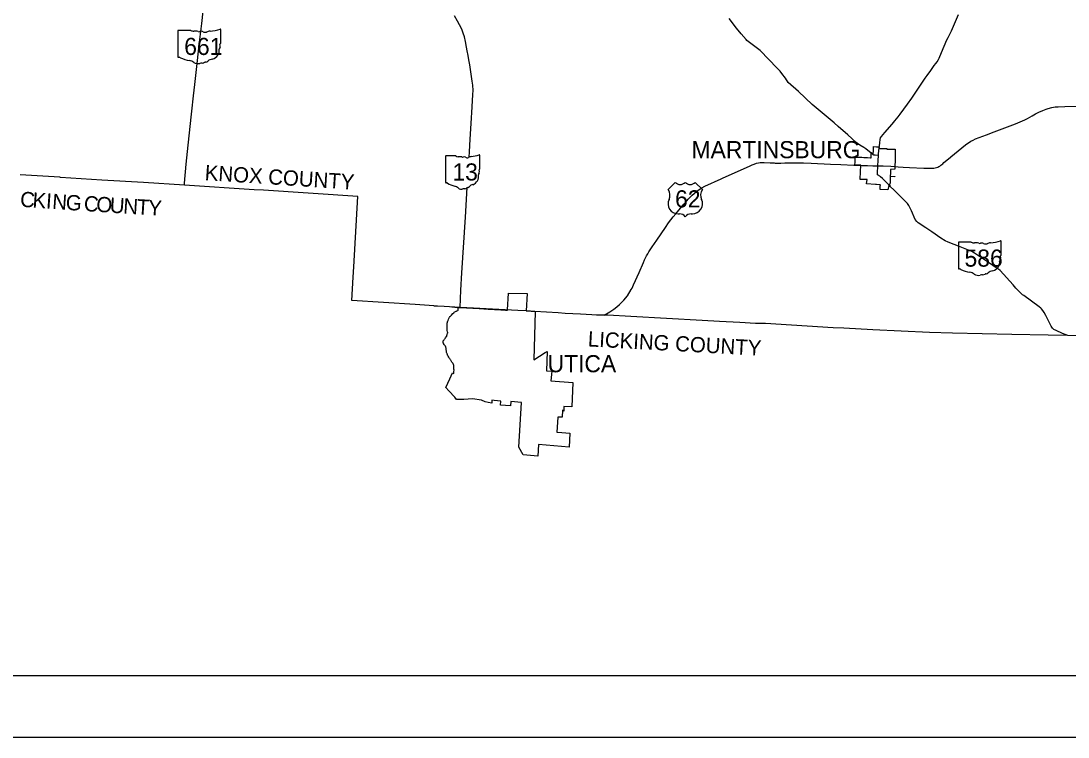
# Model space of a CAD drawing. Extents: x 1851937 to 2123937, y 789467 to 965467.
# Drawn here: x 1953112 to 2021685, y 789467 to 836328 of the extents above; entities that cross this region are included whole.
import ezdxf

# ---------------------------------------------------------------- set-up
doc = ezdxf.new("R2010")
doc.units = 0
for name, color, linetype in [('GM_X_Corporation', 7, 'Continuous'), ('GM_X_Corporation_Text', 7, 'Continuous'), ('GM_X_County', 7, 'Continuous'), ('GM_X_County_Text', 7, 'Continuous'), ('GM_X_State_Location', 7, 'Continuous'), ('GM_X_State_Route', 7, 'Continuous'), ('GM_X_State_Shield', 7, 'Continuous'), ('GM_X_US_Location', 7, 'Continuous'), ('GM_X_US_Route', 7, 'Continuous'), ('GM_X_US_Shield', 7, 'Continuous'), ('SH_Border', 7, 'Continuous'), ('SH_Cut_Line', 7, 'Continuous'), ('UT_P_Electric', 7, 'Continuous')]:
    doc.layers.add(name, color=color, linetype=linetype)

msp = doc.modelspace()

# ---------------------------------------------------------------- linework, layer by layer
at = {"layer": 'GM_X_Corporation'}
for points in [[(2008076, 825962), (2008098, 826474), (2008114, 826861), (2008115, 826891), (2008092, 826891), (2008058, 826893), (2007954, 826897), (2007949, 826897), (2007866, 826900), (2007729, 826906), (2007730, 826934), (2007734, 827061), (2007736, 827128), (2007745, 827425), (2007837, 827420), (2007875, 827418), (2007962, 827414), (2008137, 827406), (2008171, 827404), (2008319, 827397), (2008546, 827383), (2008737, 827371), (2008781, 827369), (2008792, 827637), (2008793, 827674), (2008795, 827711), (2008900, 827627), (2008926, 827606), (2008937, 827859), (2008939, 827887), (2008939, 827909), (2008945, 828104), (2009144, 828099), (2009300, 828089), (2009315, 828088), (2009313, 828078), (2009311, 828064), (2009303, 827993), (2009318, 827992), (2009815, 827981), (2009813, 827948), (2010366, 827933), (2010364, 827808), (2010364, 827788), (2010364, 827770), (2010363, 827768), (2010354, 827256), (2010353, 827179), (2010346, 826849), (2010345, 826820), (2010344, 826789), (2010344, 826754), (2010341, 826627), (2010050, 826599), (2010049, 826459), (2010048, 826438), (2010047, 826362), (2010045, 826170), (2010333, 826157), (2010332, 826137), (2010045, 826150), (2010032, 825853), (2010027, 825744), (2010060, 825712), (2010024, 825675), (2009969, 825618), (2010019, 825571), (2010020, 825571), (2010018, 825532), (2010016, 825492), (2009978, 825527), (2009945, 825559), (2009883, 825273), (2009880, 825273), (2009379, 825292), (2009391, 825529), (2009392, 825604), (2009136, 825626), (2009103, 825628), (2009075, 825630), (2008482, 825673), (2008530, 825946), (2008402, 825950)], [(1981154, 816897), (1981175, 816939), (1981192, 816964), (1981206, 816983), (1981238, 817017), (1981301, 817081), (1981398, 817177), (1981452, 817228), (1981492, 817262), (1981605, 817331), (1981628, 817344), (1981652, 817357), (1981715, 817381), (1981730, 817388), (1981736, 817397), (1981738, 817405), (1981741, 817412), (1981746, 817433), (1981742, 817466), (1981740, 817480), (1981743, 817496), (1981744, 817501), (1981746, 817515), (1981750, 817533), (1981752, 817543), (1981756, 817574), (1981870, 817569), (1983126, 817503), (1983702, 817463), (1984529, 817426), (1984709, 817415), (1984840, 817408), (1984978, 817400), (1984978, 817406), (1984970, 817421), (1985045, 818514), (1986261, 818487), (1986194, 817351), (1986529, 817328), (1986784, 817315), (1986701, 814154), (1987449, 814626), (1987568, 814701), (1987524, 813441), (1987877, 813412), (1987824, 812777), (1989249, 812678), (1989179, 811086), (1988663, 811098), (1988656, 810796), (1988626, 810826), (1988581, 810867), (1988556, 810393), (1988261, 810409), (1988203, 809429), (1988528, 809401), (1989066, 809354), (1989007, 808427), (1987000, 808604), (1986961, 807841), (1985997, 807925), (1985725, 808427), (1985892, 811352), (1985184, 811418), (1985168, 811140), (1984520, 811185), (1984536, 811454), (1984092, 811492), (1983949, 811505), (1983939, 811313), (1983720, 811361), (1983512, 811406), (1983283, 811517), (1982679, 811593), (1982111, 811563), (1981644, 811563), (1981518, 811702), (1981130, 812128), (1980942, 812333), (1981200, 812912), (1981381, 813302), (1981451, 813249), (1981464, 813380), (1981475, 813465), (1981473, 813485), (1981473, 813511), (1981470, 813528), (1981471, 813550), (1981461, 813613), (1981458, 813738), (1981458, 813755), (1981457, 813781), (1981453, 813802), (1981431, 813856), (1981424, 813873), (1981408, 813902), (1981387, 813936), (1981369, 813964), (1981340, 814006), (1981308, 814050), (1981258, 814123), (1981245, 814143), (1981217, 814189), (1981182, 814240), (1981151, 814292), (1981129, 814332), (1981097, 814386), (1981076, 814426), (1981054, 814466), (1981040, 814501), (1981029, 814528), (1981018, 814557), (1981005, 814586), (1981001, 814599), (1980988, 814633), (1980978, 814671), (1980976, 814676), (1980975, 814709), (1980973, 814725), (1980972, 814734), (1980966, 814781), (1980962, 814795), (1980960, 814803), (1980960, 814812), (1980959, 814847), (1980955, 814868), (1980955, 814871), (1980950, 814918), (1980944, 814953), (1980937, 814985), (1980930, 815003), (1980907, 815043), (1980897, 815056), (1980874, 815090), (1980857, 815111), (1980820, 815166), (1980790, 815216), (1980778, 815239), (1980769, 815264), (1980762, 815290), (1980760, 815303), (1980759, 815324), (1980759, 815344), (1980761, 815357), (1980765, 815372), (1980773, 815389), (1980784, 815406), (1980794, 815417), (1980818, 815456), (1980827, 815471), (1980858, 815512), (1980885, 815543), (1980926, 815602), (1980964, 815657), (1980979, 815678), (1980993, 815696), (1981001, 815709), (1981005, 815716), (1981013, 815737), (1981034, 815819), (1981057, 815897), (1981060, 815917), (1981060, 815938), (1981058, 815950), (1981057, 815959), (1981054, 815969), (1981049, 815983), (1981021, 816075), (1981017, 816136), (1981022, 816335), (1981027, 816546), (1981075, 816700), (1981082, 816723), (1981120, 816822), (1981138, 816864)]]:
    msp.add_lwpolyline(points, close=True, dxfattribs=at)
at = {"layer": 'GM_X_County'}
msp.add_lwpolyline([(2023355, 815717), (2021673, 815746), (2020382, 815768), (2017998, 815808), (2014115, 815904), (2012612, 815941), (2008903, 816117), (2007010, 816217), (2006295, 816254), (2001879, 816525), (2001220, 816537), (2000193, 816596), (1998868, 816656), (1997717, 816726), (1993052, 816987), (1991540, 817069), (1991299, 817080), (1990911, 817079), (1990798, 817083), (1990488, 817100), (1989753, 817138), (1988745, 817193), (1988299, 817219), (1986762, 817321), (1986194, 817351), (1985661, 817385), (1982739, 817527), (1981870, 817569), (1981756, 817574), (1981554, 817584), (1981520, 817588), (1981470, 817591), (1981338, 817602), (1981174, 817614), (1980833, 817636), (1980400, 817660), (1980203, 817671), (1980161, 817683), (1978930, 817778), (1974781, 818037), (1974871, 819560), (1974904, 820238), (1975184, 824851), (1968994, 825253), (1968379, 825285), (1963813, 825576), (1961146, 825748), (1958412, 825906), (1955709, 826088), (1955665, 826095), (1953053, 826265)], dxfattribs=at)
at = {"layer": 'GM_X_State_Route'}
for points in [[(1963814, 825573), (1963821, 825713), (1963924, 826957), (1964062, 828200), (1964292, 830227), (1964312, 830423), (1964417, 831426), (1964494, 832162), (1964673, 833738), (1964788, 834760), (1964949, 836170), (1965039, 836976)], [(2002835, 833038), (2002631, 833241), (2001524, 834387), (2000659, 835060), (2000600, 835118), (2000286, 835480), (1999975, 835858), (1999501, 836495)], [(2008869, 827617), (2008846, 827637), (2008766, 827705), (2008573, 827857), (2008446, 827953), (2008315, 828039), (2008048, 828206), (2007804, 828383), (2007255, 828870), (2006639, 829423), (2006376, 829668), (2004935, 830853), (2004028, 831707), (2003359, 832309), (2003173, 832583), (2002949, 832895), (2002835, 833038)], [(2014016, 827445), (2014974, 828216), (2015319, 828455), (2015467, 828532), (2015628, 828605), (2016352, 828881), (2016845, 829069), (2018243, 829587), (2018864, 829847), (2019038, 829940), (2019340, 830122), (2019552, 830248), (2019767, 830350), (2020034, 830468), (2020259, 830562), (2020393, 830601), (2020631, 830659), (2020843, 830698), (2021039, 830717), (2021483, 830726), (2022343, 830751)], [(2008955, 827557), (2008919, 827573), (2008869, 827617)], [(2009269, 827519), (2009052, 827535), (2008975, 827548), (2008955, 827557)], [(2009236, 826839), (2009254, 827191), (2009269, 827519)], [(2012629, 826690), (2012757, 826687), (2012841, 826691), (2012899, 826697), (2012983, 826709), (2013070, 826732), (2013150, 826764), (2013216, 826796), (2013291, 826836), (2013353, 826881), (2013477, 826985), (2013559, 827061), (2013736, 827209), (2013991, 827425), (2014016, 827445)], [(2009214, 826249), (2009208, 826311), (2009205, 826373), (2009236, 826839)], [(2009236, 826839), (2009567, 826838), (2010072, 826824), (2010351, 826801)], [(2010351, 826801), (2010567, 826783), (2010881, 826769), (2011293, 826749), (2012240, 826700), (2012629, 826690)], [(2009967, 825578), (2009526, 826014), (2009398, 826133), (2009354, 826169), (2009326, 826190), (2009284, 826215), (2009214, 826249)], [(2021674, 815743), (2021313, 815883), (2020897, 816068), (2020764, 816137), (2020663, 816226), (2020572, 816357), (2020528, 816452), (2020234, 817057), (2020120, 817257), (2020036, 817376), (2019937, 817496), (2019893, 817537), (2019797, 817623), (2018783, 818362), (2018710, 818411), (2018631, 818469), (2018555, 818548), (2018272, 818843), (2018089, 819057), (2017233, 819991), (2017124, 820085), (2017052, 820138), (2016406, 820566), (2016081, 820785), (2015551, 821143), (2015387, 821235), (2015270, 821284), (2014619, 821550), (2013838, 821853), (2013642, 821950), (2013350, 822107), (2012754, 822531), (2012373, 822789), (2011873, 823118), (2011781, 823210), (2011675, 823343), (2011423, 823892), (2011312, 824162), (2011267, 824244), (2011169, 824372), (2010907, 824640), (2010361, 825199), (2009974, 825570), (2009967, 825578)]]:
    msp.add_lwpolyline(points, dxfattribs=at)
at = {"layer": 'GM_X_State_Shield'}
for p, q in [((1963391, 835683), (1963391, 833982)), ((1964239, 835712), (1963419, 835712)), ((1966193, 834864), (1966193, 835754)), ((1966192, 834865), (1966193, 834864)), ((1980913, 827469), (1980913, 825768)), ((1981591, 827498), (1980935, 827498)), ((1983154, 826650), (1983154, 827540)), ((1983154, 826650), (1983154, 826650)), ((2014502, 821830), (2014502, 820129)), ((2015350, 821859), (2014529, 821859)), ((2017303, 821012), (2017303, 821902)), ((2017303, 821012), (2017303, 821012))]:
    msp.add_line(p, q, dxfattribs=at)
for centre, radius, start, end in [((1980939, 827472), 26, 98.1301, 188.1301), ((1981748, 827695), 252, 231.61951, 271.11188), ((1981831, 826543), 904, 80.48669, 94.98827), ((1982036, 827481), 72.7, 219.79206, 297.10237), ((1982143, 827285), 151, 54.46668, 119.14113), ((1982338, 827554), 182, 233.85621, 294.82819), ((1982659, 826978), 478, 97.34618, 120.76885), ((1982356, 829817), 2377, 275.84447, 288.90645), ((1983129, 827544), 25, 351.86209, 97.738), ((1983244, 826278), 169, 136.8065, 186.92959), ((1983149, 826585), 38.6, 107.94398, 210.33697), ((1982903, 826472), 232, 340.03296, 23.64957), ((1983128, 826647), 26.7, 289.60381, 7.73413), ((1980939, 825764), 26.2, 171.95839, 258.30661), ((1980943, 825938), 200, 267.33899, 280.60386), ((1980984, 825669), 72.1, 29.74838, 93.27175), ((1981894, 827198), 1716, 240.41292, 257.1985), ((1982489, 826165), 595, 292.30889, 8.98584), ((1981382, 825003), 537, 47.18416, 75.83597), ((1981963, 825661), 341, 230.70037, 286.29184), ((1982160, 825073), 280, 85.69512, 111.20995), ((1982185, 825534), 182, 268.77702, 315.54927), ((1982349, 825369), 51.1, 65.75173, 132.64842), ((1982327, 825603), 192, 282.87319, 323.27711), ((1982740, 825290), 326, 94.40312, 142.57675)]:
    msp.add_arc(centre, radius, start, end, dxfattribs=at)
for centre, major_axis, start_param, end_param in [((1963423, 835686), (32.5, 0), 1.712693, 3.28349), ((1964435, 835910), (315, 0), 4.042523, 4.731795), ((1964539, 834757), (1130, 0), 1.404758, 1.657858), ((1964795, 835695), (90.8, 0), 3.836095, 5.185415), ((1964929, 835499), (189, 0), 0.950623, 2.079405), ((1965173, 835768), (227, 0), 4.081561, 5.145723), ((1965574, 835193), (598, 0), 1.699011, 2.107814), ((1965195, 838031), (2971, 0), 4.814394, 5.042369), ((1966162, 835758), (31.2, 0), 6.141152, 7.989035), ((1966305, 834492), (211, 0), 2.387724, 3.262537), ((1966186, 834799), (48.3, 0), 1.883978, 3.671073), ((1965878, 834687), (290, 0), 5.934695, 6.695948), ((1966159, 834861), (33.4, 0), 5.05454, 6.418171), ((1963423, 833978), (32.7, 0), 3.00124, 4.508301), ((1963428, 834152), (250, 0), 4.665946, 4.897461), ((1963480, 833884), (90.1, 0), 0.519207, 1.627899), ((1964617, 835412), (2146, 0), 4.195997, 4.488961), ((1965361, 834379), (743, 0), 5.101752, 6.440018), ((1963977, 833217), (671, 0), 0.823519, 1.323587), ((1964704, 833875), (426, 0), 4.026481, 4.996735), ((1964950, 833287), (350, 0), 1.495662, 1.94098), ((1964981, 833748), (227, 0), 4.691044, 5.507374), ((1965186, 833583), (63.9, 0), 1.147584, 2.315152), ((1965159, 833817), (240, 0), 4.937069, 5.64225), ((1965675, 833504), (407, 0), 1.647645, 2.488434), ((2014534, 821834), (32.5, 0), 1.712693, 3.28349), ((2015545, 822057), (315, 0), 4.042523, 4.731795), ((2015649, 820904), (1130, 0), 1.404758, 1.657858), ((2015906, 821843), (90.8, 0), 3.836095, 5.185415), ((2016039, 821646), (189, 0), 0.950623, 2.079405), ((2016283, 821916), (227, 0), 4.081561, 5.145723), ((2016684, 821340), (598, 0), 1.699011, 2.107814), ((2016305, 824179), (2971, 0), 4.814394, 5.042369), ((2017272, 821905), (31.2, 0), 6.141152, 7.989035), ((2017296, 820946), (48.3, 0), 1.883978, 3.671073), ((2016989, 820834), (290, 0), 5.934695, 6.695948), ((2017270, 821008), (33.4, 0), 5.05454, 6.418171), ((2016472, 820526), (743, 0), 5.101752, 6.440018), ((2017415, 820639), (211, 0), 2.387724, 3.262537), ((2014534, 820125), (32.7, 0), 3.00124, 4.508301), ((2014539, 820299), (250, 0), 4.665946, 4.897461), ((2014590, 820031), (90.1, 0), 0.519207, 1.627899), ((2015728, 821559), (2146, 0), 4.195997, 4.488961), ((2015088, 819365), (671, 0), 0.823519, 1.323587), ((2015814, 820022), (426, 0), 4.026481, 4.996735), ((2016060, 819434), (350, 0), 1.495662, 1.94098), ((2016091, 819895), (227, 0), 4.691044, 5.507374), ((2016297, 819730), (63.9, 0), 1.147584, 2.315152), ((2016269, 819964), (240, 0), 4.937069, 5.64225), ((2016785, 819651), (407, 0), 1.647645, 2.488434)]:
    msp.add_ellipse(centre, major_axis=major_axis, ratio=0.8, start_param=start_param, end_param=end_param, dxfattribs=at)
at = {"layer": 'GM_X_US_Route'}
for points in [[(2009408, 828687), (2009460, 828766), (2009572, 828899), (2009685, 829029), (2010163, 829583), (2010352, 829802), (2010551, 830047), (2010697, 830233), (2010940, 830550), (2011171, 830875), (2011445, 831281), (2011755, 831739), (2011976, 832062), (2012336, 832579), (2012463, 832757), (2012693, 833085), (2012919, 833404), (2013022, 833545), (2013105, 833663), (2013190, 833798), (2013246, 833901), (2013293, 833999), (2013564, 834671), (2013750, 835098), (2013826, 835249), (2013936, 835464), (2013986, 835559), (2014045, 835681), (2014512, 836743)], [(2009322, 828106), (2009328, 828153), (2009352, 828343), (2009373, 828569), (2009408, 828687)], [(2009269, 827519), (2009271, 827588), (2009293, 827873), (2009308, 828000), (2009322, 828106)], [(1999099, 826057), (2000818, 826832), (2001004, 826912), (2001139, 826967), (2001283, 827013), (2001413, 827040), (2001529, 827060), (2001651, 827068), (2001776, 827072), (2002171, 827051), (2002436, 827035), (2002505, 827032), (2002609, 827029), (2002867, 827030), (2003139, 827036), (2003504, 827042), (2003957, 827047), (2004172, 827047), (2004368, 827039), (2004862, 827017), (2005270, 827000), (2005703, 826982), (2006134, 826965), (2006813, 826938), (2007660, 826898)], [(2009236, 826839), (2009254, 827191), (2009269, 827519)], [(2007660, 826898), (2007733, 826894), (2008186, 826880)], [(2008186, 826880), (2008544, 826869), (2008898, 826854), (2009236, 826839)], [(1991301, 817077), (1991678, 817301), (1991930, 817472), (1992135, 817626), (1992301, 817768), (1992456, 817919), (1992586, 818063), (1992824, 818350), (1993084, 818765), (1993130, 818832), (1993179, 818944), (1993234, 819056), (1993593, 819867), (1993882, 820530), (1993957, 820694), (1994017, 820828), (1994081, 820958), (1994157, 821089), (1994242, 821230), (1994455, 821541), (1994758, 821984), (1995328, 822816), (1995525, 823109), (1995677, 823322), (1995819, 823508), (1995991, 823711), (1996532, 824342), (1996711, 824548), (1996815, 824674), (1997059, 824919), (1997204, 825045), (1997377, 825181), (1997537, 825298), (1997701, 825401), (1997890, 825507), (1998969, 825997), (1999099, 826057)]]:
    msp.add_lwpolyline(points, dxfattribs=at)
at = {"layer": 'GM_X_US_Shield'}
for p, q in [((1995966, 825762), (1995499, 825295)), ((1997740, 825295), (1997273, 825762)), ((1996153, 823707), (1996246, 823707)), ((1996993, 823707), (1997086, 823707))]:
    msp.add_line(p, q, dxfattribs=at)
for centre, radius, start, end in [((1996293, 826095), 467, 225.573, 314.427), ((1996946, 826095), 467, 225.573, 314.427), ((1994963, 824920), 654, 334.54712, 35.00093), ((1998276, 824920), 654, 144.99907, 205.45288), ((1996145, 824361), 654, 154.83192, 270.63826), ((1997094, 824361), 654, 269.36174, 25.16808), ((1996246, 823240), 467, 36.8699, 90), ((1996993, 823240), 467, 90, 143.1301)]:
    msp.add_arc(centre, radius, start, end, dxfattribs=at)
at = {"layer": 'SH_Border'}
msp.add_lwpolyline([(1863937, 961467), (2119937, 961467), (2119937, 793467), (1863937, 793467)], close=True, dxfattribs=at)
at = {"layer": 'SH_Cut_Line'}
msp.add_lwpolyline([(1851937, 789467), (2123937, 789467), (2123937, 965467), (1851937, 965467)], close=True, dxfattribs=at)
at = {"layer": 'UT_P_Electric'}
for points in [[(1982465, 827415), (1982486, 827756), (1982523, 828591), (1982593, 829621), (1982662, 830704), (1982704, 831510), (1982719, 831786), (1982701, 832125), (1982672, 832396), (1982505, 833455), (1982444, 833777), (1982402, 834058), (1982341, 834368), (1982280, 834603), (1982221, 834983), (1982152, 835288), (1982076, 835524), (1982000, 835723), (1981909, 835922), (1981831, 836077), (1981708, 836318), (1981507, 836674)], [(1981992, 819839), (1981992, 819844), (1982226, 823484), (1982342, 825419)], [(1981871, 817566), (1981916, 818701), (1981992, 819839)]]:
    msp.add_lwpolyline(points, dxfattribs=at)

# ---------------------------------------------------------------- texts
at = {"layer": 'GM_X_Corporation_Text'}
for s, p in [('MARTINSBURG', (1997028, 827347)), ('UTICA', (1987600, 813338))]:
    msp.add_text(s, height=1120, rotation=0.00001, dxfattribs=at).set_placement(p)
at = {"layer": 'GM_X_County_Text'}
for s, rotation, p in [('KNOX COUNTY', 356.32859, (1965127, 825913)), ('C', 356.11482, (1953033, 824172)), ('K', 356.09868, (1953845, 824117)), ('I', 356.06743, (1954728, 824057)), ('N', 356.02347, (1955136, 824028)), ('G', 356.39822, (1956025, 823967)), ('C', 356.42437, (1957211, 823892)), ('O', 356.42451, (1958024, 823841)), ('U', 356.42519, (1958906, 823786)), ('N', 356.4256, (1959789, 823731)), ('T', 356.42512, (1960672, 823676)), ('Y', 356.4256, (1961418, 823629)), ('LICKING COUNTY', 356.91356, (1990219, 815033))]:
    msp.add_text(s, height=1000, rotation=rotation, dxfattribs=at).set_placement(p)
at = {"layer": 'GM_X_State_Location'}
for s, p in [('661', (1964420, 834412)), ('13', (1982161, 826338)), ('586', (2015689, 820381))]:
    msp.add_text(s, height=1, rotation=0.00001, dxfattribs=at).set_placement(p)
for s, p in [('s', (1964773, 834485)), ('r', (1964773, 834485)), ('s', (1982413, 826411)), ('r', (1982413, 826411)), ('s', (2016042, 820454)), ('r', (2016042, 820454))]:
    msp.add_text(s, height=1, dxfattribs=at).set_placement(p)
at = {"layer": 'GM_X_State_Shield'}
for s, p in [('661', (1963804, 834102)), ('13', (1981369, 825887)), ('586', (2014905, 820249))]:
    msp.add_text(s, height=1120.7, dxfattribs=at).set_placement(p)
at = {"layer": 'GM_X_US_Location'}
msp.add_text('62', height=1, rotation=0.00001, dxfattribs=at).set_placement((1996413, 824033))
for s in ['0', '/']:
    msp.add_text(s, height=1, dxfattribs=at).set_placement((1996619, 824240))
at = {"layer": 'GM_X_US_Shield'}
msp.add_text('62', height=1120.7, dxfattribs=at).set_placement((1995950, 824127))

doc.saveas('drawing.dxf')
